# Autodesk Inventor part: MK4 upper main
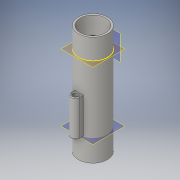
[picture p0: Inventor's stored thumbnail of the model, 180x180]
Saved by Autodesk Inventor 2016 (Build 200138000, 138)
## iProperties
Created: 2015-09
Part Number: MK4 upper main
Material: Generic
Document SubType Name: Modeling
Designer: lwilliams6899
Density: 1 g/cm^3
Appearance: Default
Author: lwilliams6899
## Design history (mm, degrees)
sketch "Sketch1"
  geometry: C1 r 12.7 at (0, 0); C2 r 10.097 at (0, 0); 1 further point
  constraints: 2 centre point, 2 coincident
  dimensions: "d0" = 25.4 diameter of C1; "d1" = 20.193 diameter of C2
extrude "Extrusion1" new body sketch "Sketch1" distance "d2" = 95.25; taper "d3" = 0 deg
workplane "Work Plane1"
sketch "Sketch2"
  geometry: L1 (-3.81, 15.177)-(-3.81, 12.115); L2 (3.81, 12.115)-(3.81, 15.177); C1 r 10.097 at (0, 0) reference; C2 r 2.159 at (0, 15.177); A1 r 12.7 centre (0, 0) between (-3.81, 12.115) and (3.81, 12.115) reference; A2 r 3.81 centre (0, 15.177) between (3.81, 15.177) and (-3.81, 15.177); 1 further point
  constraints: 4 end point, 4 point on circle, 2 centre point, 1 coincident, 1 vertical
  dimensions: "d5" = 4.318 diameter of C2; "d6" = 7.62 diameter of A2
extrude "Extrusion2" join sketch "Sketch2" distance "d7" = 31.75; taper "d8" = 0 deg
fillet "Fillet1" dims "d9" = 0.635
workplane "Work Plane2"
sketch "Sketch3"
  geometry: L1 (0, 4.039)-(0, 12.7); L2 (0, 12.7)-(-3.846, 12.7); 2 further points
  constraints: 4 end point, 2 horizontal, 1 vertical, 1 vertical alignment, 1 other
workplane "Work Plane3"
sketch "Sketch4"
  geometry: L1 (-1.562, 0.395)-(1.59, 0.395); L2 (1.59, 0.395)-(1.59, 1.818); L3 (1.59, 1.818)-(-1.562, 1.818); L4 (-1.562, 1.818)-(-1.562, 0.395); L5 (-1.593, -1.87)-(1.59, -1.87); L6 (1.59, -1.87)-(1.59, -0.645); L7 (1.59, -0.645)-(-1.593, -0.645); L8 (-1.593, -0.645)-(-1.593, -1.87); 1 further point
  constraints: 16 end point, 4 parallel, 2 horizontal, 2 perpendicular, 1 point on line
extrude "Extrusion3" cut sketch "Sketch4" distance "d11" = 12.7; taper "d12" = 0 deg
fillet "Fillet2" dims "d13" = 0.4318
sketch "Sketch5"
  geometry: C1 r 11.113 at (0, 0); 1 further point
  constraints: 1 centre point, 1 coincident
  dimensions: "d14" = 22.225 diameter of C1
extrude "Extrusion4" cut sketch "Sketch5" distance "d15" = 50.8; taper "d16" = -1.5 deg
sketch "Sketch6"
  geometry: C1 r 11.112 at (0, 0); 1 further point
  constraints: 1 centre point, 1 coincident
  dimensions: "d19" = 22.225 diameter of C1
extrude "Extrusion5" cut sketch "Sketch6" distance "d17" = 15.24; taper "d18" = 0 deg
sketch "Sketch7"
  geometry: 1 further point
body "Solid1"
node "Projected Loop1"
other parameters: "d4" = -19.05, "d10" = -17.78
